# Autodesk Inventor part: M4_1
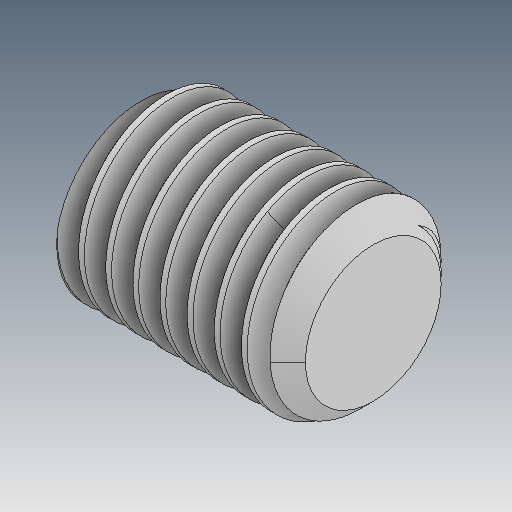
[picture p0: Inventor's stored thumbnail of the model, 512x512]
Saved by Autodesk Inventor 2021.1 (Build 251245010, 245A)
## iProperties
Created: 2019-04
Part Number: M4_1
Material: Ogólny
Document SubType Name: Modeling
Designer: user
Density: 1 g/cm^3
Appearance: Domyślna
Author: user
Revision Number: ÈÎºÎ
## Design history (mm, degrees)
feature "ÊäÈë1"
node "Bryła1"
